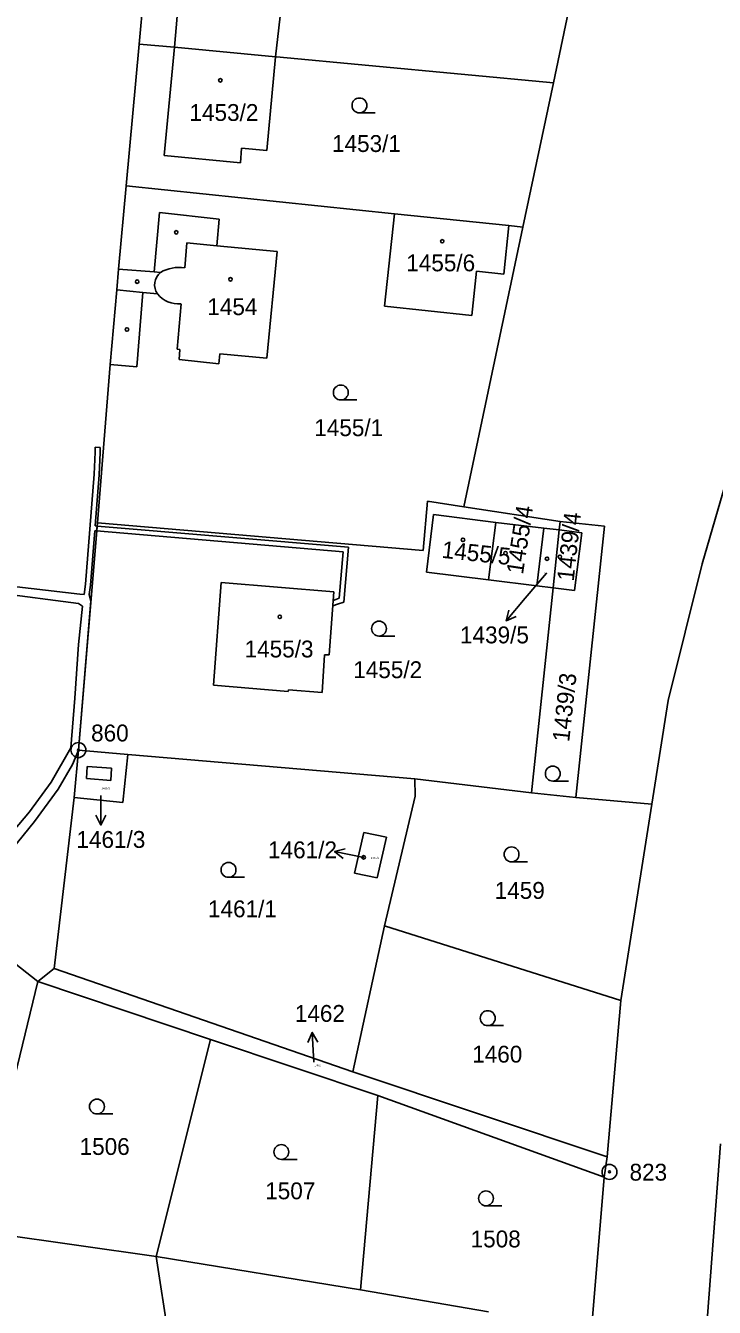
# Model space of a CAD drawing. Extents: x -755819 to -753140, y -1169796 to -1166000.
# Drawn here: x -755627 to -755557.5, y -1167579.9 to -1167450.7 of the extents above; entities that cross this region are included whole.
import ezdxf

# ---------------------------------------------------------------- set-up
doc = ezdxf.new("R2010")
doc.units = 0
for name, color, linetype in [('Vrstva 1', 7, 'Continuous'), ('Vrstva 16', 7, 'Continuous'), ('Vrstva 17', 7, 'Continuous'), ('Vrstva 18', 7, 'Continuous'), ('Vrstva 19', 7, 'Continuous'), ('Vrstva 24', 7, 'Continuous'), ('Vrstva 25', 7, 'Continuous'), ('Vrstva 27', 7, 'Continuous'), ('Vrstva 4', 7, 'Continuous')]:
    doc.layers.add(name, color=color, linetype=linetype)

msp = doc.modelspace()

# ---------------------------------------------------------------- linework, layer by layer
at = {"layer": 'Vrstva 1'}
for p, q in [((-755614.27, -1167438.02), (-755615.55, -1167452.53)), ((-755570.81, -1167442.32), (-755573.78, -1167456.41)), ((-755601.13, -1167447.92), (-755601.81, -1167453.79)), ((-755615.55, -1167452.53), (-755616.86, -1167466.82)), ((-755615.55, -1167452.53), (-755611.99, -1167452.83)), ((-755613.03, -1167463.76), (-755611.99, -1167452.83)), ((-755611.99, -1167452.83), (-755601.81, -1167453.79)), ((-755601.81, -1167453.79), (-755602.7, -1167463.24)), ((-755601.81, -1167453.79), (-755601.72, -1167453.79)), ((-755573.78, -1167456.41), (-755601.72, -1167453.79)), ((-755573.78, -1167456.41), (-755576.85, -1167470.96)), ((-755605.33, -1167464.49), (-755613.03, -1167463.76)), ((-755605.23, -1167463), (-755605.33, -1167464.49)), ((-755602.7, -1167463.24), (-755605.23, -1167463)), ((-755616.86, -1167466.82), (-755617.66, -1167475.19)), ((-755589.82, -1167469.62), (-755616.86, -1167466.82)), ((-755614.04, -1167475.48), (-755613.52, -1167469.49)), ((-755613.52, -1167469.49), (-755607.49, -1167470.17)), ((-755607.49, -1167470.17), (-755607.72, -1167472.84)), ((-755589.82, -1167469.62), (-755590.81, -1167478.94)), ((-755578.28, -1167470.81), (-755589.82, -1167469.62)), ((-755576.85, -1167470.96), (-755582.81, -1167499.16)), ((-755578.79, -1167475.71), (-755578.28, -1167470.81)), ((-755576.85, -1167470.96), (-755578.28, -1167470.81)), ((-755607.72, -1167472.84), (-755601.65, -1167473.43)), ((-755601.65, -1167473.43), (-755602.68, -1167484.19)), ((-755617.66, -1167475.19), (-755617.8, -1167477.28)), ((-755617.66, -1167475.19), (-755614.04, -1167475.48)), ((-755582.01, -1167479.87), (-755581.53, -1167475.42)), ((-755581.53, -1167475.42), (-755578.79, -1167475.71)), ((-755617.8, -1167477.28), (-755618.49, -1167484.81)), ((-755615.79, -1167485.06), (-755615.18, -1167477.55)), ((-755615.18, -1167477.55), (-755613.72, -1167477.7)), ((-755611.73, -1167483.28), (-755611.34, -1167478.7)), ((-755590.81, -1167478.94), (-755582.01, -1167479.87)), ((-755611.46, -1167483.3), (-755611.73, -1167483.28)), ((-755611.51, -1167484.3), (-755611.46, -1167483.3)), ((-755607.52, -1167484.75), (-755611.51, -1167484.3)), ((-755607.42, -1167483.73), (-755607.52, -1167484.75)), ((-755602.68, -1167484.19), (-755607.42, -1167483.73)), ((-755618.49, -1167484.81), (-755619.78, -1167500.77)), ((-755618.49, -1167484.81), (-755615.79, -1167485.06)), ((-755553.99, -1167488.43), (-755558.78, -1167504.92)), ((-755586.9, -1167503.58), (-755586.48, -1167498.6)), ((-755586.48, -1167498.6), (-755582.81, -1167499.16)), ((-755586.58, -1167505.74), (-755585.87, -1167499.95)), ((-755585.87, -1167499.95), (-755579.6, -1167500.73)), ((-755573.1, -1167500.65), (-755582.81, -1167499.16)), ((-755621.69, -1167523.69), (-755619.78, -1167500.77)), ((-755586.9, -1167503.58), (-755619.78, -1167500.77)), ((-755579.6, -1167500.73), (-755580.31, -1167506.52)), ((-755579.6, -1167500.73), (-755574.73, -1167501.31)), ((-755574.73, -1167501.31), (-755575.45, -1167507.12)), ((-755574.73, -1167501.31), (-755573.19, -1167501.5)), ((-755573.1, -1167500.65), (-755573.19, -1167501.5)), ((-755568.62, -1167501.12), (-755573.1, -1167500.65)), ((-755571.52, -1167528.48), (-755568.62, -1167501.12)), ((-755573.19, -1167501.5), (-755573.81, -1167507.32)), ((-755570.92, -1167501.78), (-755573.19, -1167501.5)), ((-755570.92, -1167501.78), (-755571.64, -1167507.59)), ((-755558.78, -1167504.92), (-755562.2, -1167518.7)), ((-755580.31, -1167506.52), (-755586.58, -1167505.74)), ((-755575.45, -1167507.12), (-755580.31, -1167506.52)), ((-755607.3, -1167506.8), (-755608.06, -1167517.15)), ((-755607.3, -1167506.8), (-755595.94, -1167507.75)), ((-755595.94, -1167507.75), (-755596.4, -1167514.1)), ((-755573.81, -1167507.32), (-755576, -1167528.01)), ((-755575.45, -1167507.12), (-755573.81, -1167507.32)), ((-755571.64, -1167507.59), (-755573.81, -1167507.32)), ((-755597.09, -1167517.89), (-755596.88, -1167514.09)), ((-755596.88, -1167514.09), (-755596.4, -1167514.1)), ((-755608.06, -1167517.15), (-755600.52, -1167517.77)), ((-755600.52, -1167517.77), (-755600.5, -1167517.61)), ((-755600.5, -1167517.61), (-755597.09, -1167517.89)), ((-755562.2, -1167518.7), (-755563.85, -1167529.14)), ((-755621.69, -1167523.69), (-755622.12, -1167528.48)), ((-755616.69, -1167524.12), (-755621.69, -1167523.69)), ((-755616.69, -1167524.12), (-755617.22, -1167528.97)), ((-755587.76, -1167526.59), (-755616.69, -1167524.12)), ((-755587.76, -1167526.59), (-755587.73, -1167528.34)), ((-755587.76, -1167526.59), (-755576, -1167528.01)), ((-755624.12, -1167545.72), (-755622.12, -1167528.48)), ((-755617.22, -1167528.97), (-755622.12, -1167528.48)), ((-755587.73, -1167528.34), (-755590.82, -1167541.42)), ((-755571.52, -1167528.48), (-755576, -1167528.01)), ((-755563.85, -1167529.14), (-755571.52, -1167528.48)), ((-755566.99, -1167548.94), (-755563.85, -1167529.14)), ((-755593.85, -1167536.09), (-755592.89, -1167531.99)), ((-755592.89, -1167531.99), (-755590.61, -1167532.47)), ((-755590.61, -1167532.47), (-755591.57, -1167536.57)), ((-755591.57, -1167536.57), (-755593.85, -1167536.09)), ((-755625.77, -1167547.03), (-755632.15, -1167542.01)), ((-755594.02, -1167556.12), (-755590.82, -1167541.42)), ((-755590.82, -1167541.42), (-755566.99, -1167548.94)), ((-755625.77, -1167547.03), (-755624.12, -1167545.72)), ((-755624.12, -1167545.72), (-755594.02, -1167556.12)), ((-755625.77, -1167547.03), (-755631.91, -1167572.18)), ((-755608.35, -1167552.87), (-755625.77, -1167547.03)), ((-755566.99, -1167548.94), (-755568.37, -1167564.71)), ((-755613.85, -1167574.74), (-755608.35, -1167552.87)), ((-755608.35, -1167552.87), (-755591.48, -1167558.52)), ((-755568.37, -1167564.71), (-755594.02, -1167556.12)), ((-755591.48, -1167558.52), (-755593.22, -1167578.1)), ((-755591.48, -1167558.52), (-755568.64, -1167566.74)), ((-755556.91, -1167563.38), (-755558.38, -1167582.5)), ((-755568.37, -1167564.71), (-755568.64, -1167566.74)), ((-755568.64, -1167566.74), (-755569.93, -1167582.11)), ((-755613.85, -1167574.74), (-755631.91, -1167572.18)), ((-755612.16, -1167585.56), (-755613.85, -1167574.74)), ((-755593.22, -1167578.1), (-755613.85, -1167574.74)), ((-755580.32, -1167580.32), (-755593.22, -1167578.1))]:
    msp.add_line(p, q, dxfattribs=at)
msp.add_arc((-755611.59, -1167475.96), 2.75, 219.259, 275.1598, dxfattribs=at)
at = {"layer": 'Vrstva 16'}
for p, q in [((-755574.49, -1167505.87), (-755576.61, -1167508.37)), ((-755578.55, -1167510.66), (-755576.61, -1167508.37)), ((-755619.42, -1167531.26), (-755619.42, -1167528.26)), ((-755595.85, -1167533.93), (-755592.91, -1167534.53)), ((-755598.1, -1167552.15), (-755597.94, -1167555.15))]:
    msp.add_line(p, q, dxfattribs=at)
for points in [[(-755577.52, -1167510.22), (-755578.55, -1167510.66), (-755578.28, -1167509.57)], [(-755618.92, -1167530.26), (-755619.42, -1167531.26), (-755619.92, -1167530.26)], [(-755594.97, -1167534.62), (-755595.85, -1167533.93), (-755594.77, -1167533.64)], [(-755598.55, -1167553.18), (-755598.1, -1167552.15), (-755597.55, -1167553.13)]]:
    msp.add_lwpolyline(points, dxfattribs=at)
at = {"layer": 'Vrstva 24'}
for centre, radius in [((-755621.69, -1167523.69), 0.75), ((-755621.69, -1167523.69), 0.1), ((-755568.12, -1167566.22), 0.75), ((-755568.12, -1167566.22), 0.1)]:
    msp.add_circle(centre, radius, dxfattribs=at)
at = {"layer": 'Vrstva 25'}
for p, q in [((-755593.34, -1167459.45), (-755591.74, -1167459.45)), ((-755595.22, -1167488.39), (-755593.62, -1167488.39)), ((-755591.37, -1167512.19), (-755589.77, -1167512.19)), ((-755573.84, -1167526.81), (-755572.24, -1167526.81)), ((-755578, -1167534.96), (-755576.4, -1167534.96)), ((-755606.55, -1167536.52), (-755604.95, -1167536.52)), ((-755580.4, -1167551.47), (-755578.8, -1167551.47)), ((-755619.82, -1167560.38), (-755618.22, -1167560.38)), ((-755601.22, -1167564.96), (-755599.62, -1167564.96)), ((-755580.58, -1167569.64), (-755578.98, -1167569.64))]:
    msp.add_line(p, q, dxfattribs=at)
for centre, radius in [((-755607.37, -1167456.16), 0.175), ((-755593.34, -1167458.7), 0.75), ((-755611.82, -1167471.49), 0.175), ((-755584.99, -1167472.39), 0.175), ((-755615.76, -1167476.47), 0.175), ((-755606.35, -1167476.23), 0.175), ((-755616.79, -1167481.29), 0.175), ((-755595.22, -1167487.64), 0.75), ((-755582.9, -1167502.49), 0.175), ((-755578.61, -1167503.84), 0.175), ((-755574.42, -1167504.4), 0.175), ((-755573.12, -1167504.21), 0.175), ((-755601.38, -1167510.26), 0.175), ((-755591.37, -1167511.44), 0.75), ((-755573.84, -1167526.06), 0.75), ((-755578, -1167534.21), 0.75), ((-755592.92, -1167534.51), 0.175), ((-755606.55, -1167535.77), 0.75), ((-755580.4, -1167550.72), 0.75), ((-755619.82, -1167559.63), 0.75), ((-755601.22, -1167564.21), 0.75), ((-755580.58, -1167568.89), 0.75)]:
    msp.add_circle(centre, radius, dxfattribs=at)
at = {"layer": 'Vrstva 27'}
for p, q in [((-755620.01, -1167493.66), (-755619.99, -1167493.16)), ((-755619.99, -1167493.16), (-755619.49, -1167493.18)), ((-755619.49, -1167493.18), (-755619.51, -1167493.68)), ((-755620.1, -1167495.89), (-755620.01, -1167493.66)), ((-755619.51, -1167493.68), (-755619.6, -1167495.95)), ((-755620.97, -1167506.95), (-755620.1, -1167495.89)), ((-755619.6, -1167495.95), (-755620, -1167501.08)), ((-755620, -1167501.08), (-755619.81, -1167501.1)), ((-755619.85, -1167501.6), (-755619.81, -1167501.1)), ((-755619.81, -1167501.1), (-755619.85, -1167501.6)), ((-755619.81, -1167501.1), (-755594.46, -1167503.23)), ((-755620.04, -1167501.58), (-755620.47, -1167507.07)), ((-755619.85, -1167501.6), (-755620.04, -1167501.58)), ((-755595, -1167503.69), (-755619.85, -1167501.6)), ((-755595.4, -1167508.39), (-755595, -1167503.69)), ((-755594.46, -1167503.23), (-755594.92, -1167508.77)), ((-755632.52, -1167506.68), (-755621.55, -1167507.96)), ((-755621.68, -1167508.9), (-755632.41, -1167507.52)), ((-755621.12, -1167507.99), (-755620.97, -1167506.95)), ((-755620.47, -1167507.07), (-755620.61, -1167508.02)), ((-755620.44, -1167508.63), (-755621.69, -1167523.69)), ((-755621.27, -1167509.19), (-755621.68, -1167508.9)), ((-755621.55, -1167507.96), (-755621.12, -1167507.99)), ((-755620.61, -1167508.02), (-755620.44, -1167508.63)), ((-755596.04, -1167509.15), (-755596, -1167508.6)), ((-755595.57, -1167508.99), (-755596.04, -1167509.15)), ((-755596, -1167508.6), (-755595.73, -1167508.51)), ((-755595.73, -1167508.51), (-755595.4, -1167508.39)), ((-755594.92, -1167508.77), (-755595.57, -1167508.99)), ((-755621.68, -1167513.03), (-755621.27, -1167509.19)), ((-755622.05, -1167518.46), (-755621.68, -1167513.03)), ((-755622.47, -1167523.46), (-755622.05, -1167518.46)), ((-755624.44, -1167526.92), (-755622.47, -1167523.46)), ((-755621.69, -1167523.69), (-755622.27, -1167525.16)), ((-755622.27, -1167525.16), (-755623.72, -1167527.62)), ((-755626.61, -1167529.91), (-755624.44, -1167526.92)), ((-755623.72, -1167527.62), (-755626.12, -1167530.89)), ((-755629.31, -1167533.11), (-755626.61, -1167529.91)), ((-755626.12, -1167530.89), (-755628.41, -1167533.7))]:
    msp.add_line(p, q, dxfattribs=at)
at = {"layer": 'Vrstva 4'}
for p, q in [((-755611.25, -1167443.73), (-755611.99, -1167452.83)), ((-755610.97, -1167475.08), (-755610.76, -1167472.55)), ((-755610.76, -1167472.55), (-755607.72, -1167472.84)), ((-755613.4, -1167475.53), (-755614.04, -1167475.48)), ((-755615.18, -1167477.55), (-755617.8, -1167477.28)), ((-755620.89, -1167526.57), (-755620.8, -1167525.35)), ((-755620.8, -1167525.35), (-755618.34, -1167525.52)), ((-755618.34, -1167525.52), (-755618.43, -1167526.75)), ((-755618.43, -1167526.75), (-755620.89, -1167526.57))]:
    msp.add_line(p, q, dxfattribs=at)
for centre, radius, start, end in [((-755611.58, -1167478.6), 3.57, 80.2449, 120.7381), ((-755612.37, -1167476.79), 1.63, 129.2479, 213.9747)]:
    msp.add_arc(centre, radius, start, end, dxfattribs=at)

# ---------------------------------------------------------------- texts
at = {"layer": 'Vrstva 16'}
for s, p in [('1439/5', (-755583.2, -1167512.93)), ('1461/3', (-755621.89, -1167533.55)), ('1461/2', (-755602.56, -1167534.6)), ('1462', (-755599.86, -1167551.09))]:
    msp.add_text(s, height=1.7, dxfattribs=at).set_placement(p)
at = {"layer": 'Vrstva 17'}
for s, p in [('860', (-755620.41, -1167522.82)), ('823', (-755566.1, -1167567.1))]:
    msp.add_text(s, height=1.7, dxfattribs=at).set_placement(p)
at = {"layer": 'Vrstva 18'}
for s, height, p in [('1453/1', 1.7, (-755596.11, -1167463.39)), ('1455/1', 1.7, (-755597.9, -1167492.04)), ('1455/2', 1.7, (-755593.97, -1167516.44)), ('1461/3', 0.2, (-755619.37, -1167527.65)), ('1459', 1.7, (-755579.7, -1167538.69)), ('1461/1', 1.7, (-755608.62, -1167540.55)), ('1460', 1.7, (-755581.97, -1167555.2)), ('1462', 0.2, (-755597.87, -1167555.56)), ('1506', 1.7, (-755621.57, -1167564.51)), ('1507', 1.7, (-755602.85, -1167568.98)), ('1508', 1.7, (-755582.13, -1167573.83))]:
    msp.add_text(s, height=height, dxfattribs=at).set_placement(p)
msp.add_text('1439/3', height=1.7, rotation=83.7091, dxfattribs=at).set_placement((-755572.19, -1167522.93))
at = {"layer": 'Vrstva 19'}
for s, height, p in [('1453/2', 1.7, (-755610.49, -1167460.26)), ('1455/6', 1.7, (-755588.62, -1167475.42)), ('1454', 1.7, (-755608.69, -1167479.84)), ('1439/5', 0.1, (-755574.72, -1167505.87)), ('1455/3', 1.7, (-755604.93, -1167514.35)), ('1461/2', 0.2, (-755592.21, -1167534.66))]:
    msp.add_text(s, height=height, dxfattribs=at).set_placement(p)
for s, rotation, p in [('1455/4', 81.4173, (-755576.85, -1167506.04)), ('1439/4', 83.881, (-755571.73, -1167506.72)), ('1455/5', 353.916, (-755585.1, -1167504.3))]:
    msp.add_text(s, height=1.7, rotation=rotation, dxfattribs=at).set_placement(p)

doc.saveas('drawing.dxf')
